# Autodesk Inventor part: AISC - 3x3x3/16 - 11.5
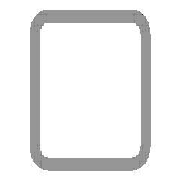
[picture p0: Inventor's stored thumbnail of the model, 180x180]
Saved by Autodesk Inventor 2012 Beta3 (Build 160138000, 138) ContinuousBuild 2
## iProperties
IsCustomPart: 1
Created: 2011-01
Part Number: AISC - 3x3x3/16 - 11.5
Material: Steel, Mild
Description: Tube
Document SubType Name: Modeling
Standard: ANSI
Designer: Beta-8540w
Standards Organization: ANSI
Language: en-US
Size Designation: 3x3x3/16
Categories: <MemberInstance><Categories><Category DisplayName="Structural Shapes" InternalName="089c4875-fa83-4c05-b084-43b9cc11f5ed" Mnemonic="GRDR"><CategoryParameter Dis
Stock Number: 3x3x3/16
Density: 7.86 g/cm^3
_CCFamilyMember: 9
_CCFamilyDisplayName: ANSI AISC (Square) - Tube
_FrameMemberDoc: Frame Member File
_Version: 15.0.0
_GetPNFromCC: 1
G_L: 11.500 in
G_W: 3.000 in
G_H: 3.000 in
Author: Beta-8540w
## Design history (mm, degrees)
node "Start plane"
node "End plane"
sketch "Sketch"
  geometry: L1 (-38.1, -28.575)-(-38.1, 28.575); L2 (-28.575, 38.1)-(28.575, 38.1); L3 (38.1, 28.575)-(38.1, -28.575); L4 (28.575, -38.1)-(-28.575, -38.1); L5 (-28.575, 33.337)-(28.575, 33.338); L6 (33.338, 28.575)-(33.338, -28.575); L7 (28.575, -33.337)-(-28.575, -33.338); L8 (-33.338, -28.575)-(-33.338, 28.575); L9 (0, 56.102)-(0, -56.102) reference; L10 (-56.102, 0)-(56.102, 0) reference; A1 r 9.525 centre (-28.575, -28.575) between (-38.1, -28.575) and (-28.575, -38.1); A2 r 9.525 centre (-28.575, 28.575) between (-28.575, 38.1) and (-38.1, 28.575); A3 r 9.525 centre (28.575, 28.575) between (38.1, 28.575) and (28.575, 38.1); A4 r 9.525 centre (28.575, -28.575) between (28.575, -38.1) and (38.1, -28.575); A5 r 4.763 centre (-28.575, 28.575) between (-28.575, 33.337) and (-33.338, 28.575); A6 r 4.763 centre (28.575, 28.575) between (33.338, 28.575) and (28.575, 33.338); A7 r 4.763 centre (28.575, -28.575) between (28.575, -33.337) and (33.338, -28.575); A8 r 4.763 centre (-28.575, -28.575) between (-33.338, -28.575) and (-28.575, -33.338)
  constraints: 16 end point, 16 point on circle, 8 centre point, 8 tangent, 4 parallel, 3 equal radius, 2 perpendicular, 7 other
  dimensions: "d10" = 76.2 distance between parallel lines of L2 L4 (= G_H); "d11" = 76.2 distance between parallel lines of L1 L3 (= G_W); "d12" = 4.7625 distance between parallel lines of L3 L6 (= G_T); "d15" = 38.1 distance between parallel lines of L2 L10 (= 0.5 x d10); "d16" = 38.1 distance between parallel lines of L9 L3 (= 0.5 x d11); "d17" = 9.525 radius of A1 (= G_IR)
extrude "Body" new body sketch "Sketch" stored distance "d3" = 292.1 (= G_L); taper "d4" = 0 deg
node "Driven Length"
  sketch "Sketch3"
    geometry: L1 (0, 0)-(10, 0) reference
    constraints: 2 end point, 1 horizontal
  workplane "Work Plane3"
  sketch "Sketch4"
    geometry: L1 (-2, -38.1)-(12, -38.1) reference; L2 (-2, 254)-(12, 254) reference
    dimensions: "d19" = 292.1 distance between parallel lines of L1 L2 (derived)
workplane "Work Plane4"
split "Split1"
body "Solid1"
other parameters: "G_W" = 76.2 [user parameter; used in 1 equation term], "G_H" = 76.2 [user parameter; used in 1 equation term], "G_T" = 4.7625 [user parameter; used in 1 equation term], "G_IR" = 9.525 [user parameter; used in 1 equation term], "G_L" = 292.1 (= d19) [user parameter; used in 1 equation term], "G_OFFSET_START" = 38.1 [user parameter; used in 1 equation term], "G_OFFSET_END" = 0 [user parameter; used in 1 equation term], "d13" = -38.1 (= -G_OFFSET_START), "d14" = 254 (= G_OFFSET_END + B_L), "B_L" = 254 [user parameter; used in 1 equation term], "d18" = 90 deg
